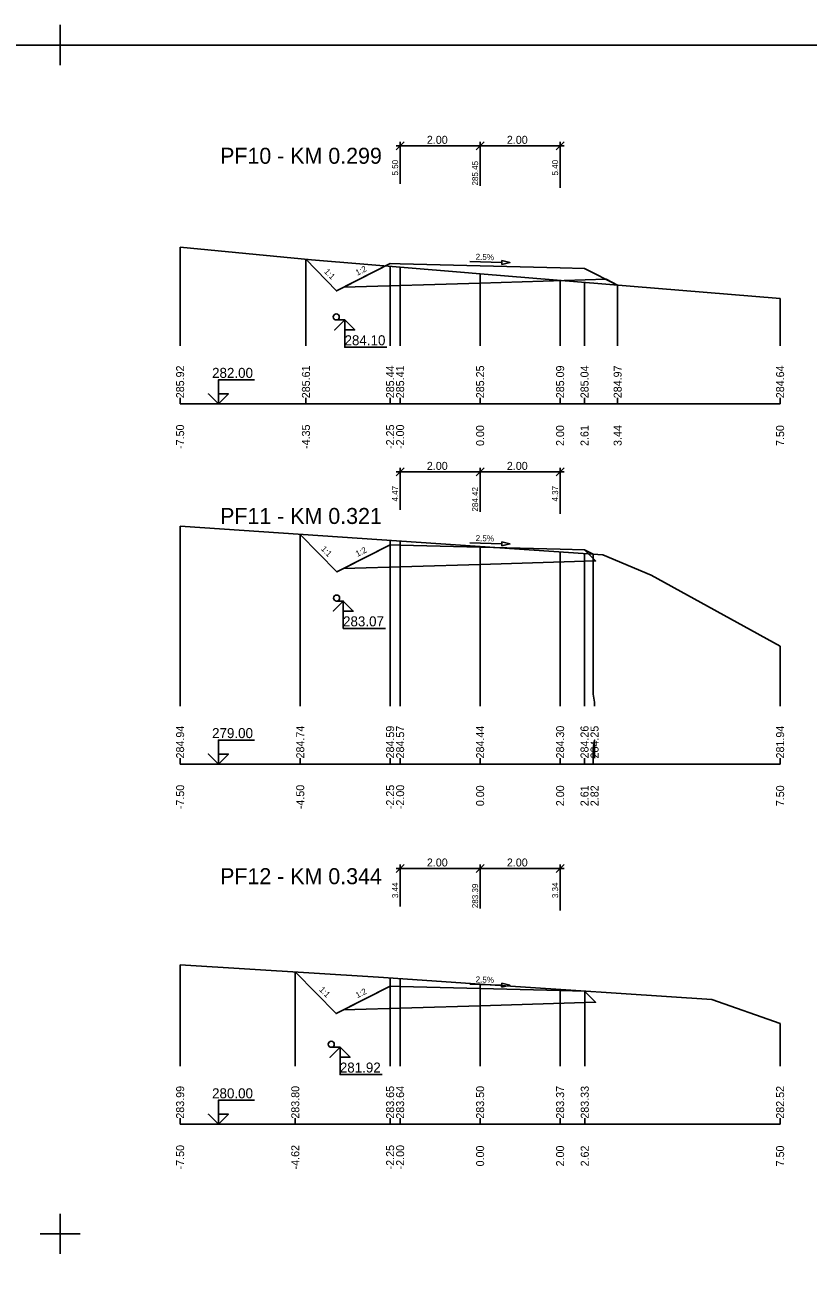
# Model space of a CAD drawing. Extents: x -5 to 1895, y -2 to 602.
# Drawn here: x 621.2 to 817, y 289.4 to 601.7 of the extents above; entities that cross this region are included whole.
import ezdxf

# ---------------------------------------------------------------- set-up
doc = ezdxf.new("R2010")
doc.units = 0
for name, color, linetype in [('KOTA', 7, 'Continuous'), ('KOTA_DELKY', 7, 'Continuous'), ('KOTA_DELKY_CONT', 7, 'Continuous'), ('KRIZENI', 7, 'Continuous'), ('NS_TELESO_VOZOVKY', 7, 'Continuous'), ('NS_V_PF', 7, 'Continuous'), ('REZY_PF_PUVODNI', 7, 'Continuous'), ('SESTAVY_REZU_PF', 7, 'Continuous'), ('SKLON', 7, 'Continuous'), ('SVK', 7, 'Continuous')]:
    doc.layers.add(name, color=color, linetype=linetype)

msp = doc.modelspace()

# ---------------------------------------------------------------- linework, layer by layer
for p, q in [((630, 601.67), (630, 591.67)), ((630, 601.67), (630, 591.67)), ((630, 601.67), (630, 591.67)), ((630, 601.67), (630, 591.67)), ((630, 601.67), (630, 591.67)), ((630, 601.67), (630, 591.67)), ((630, 601.67), (630, 591.67)), ((630, 601.67), (630, 591.67)), ((630, 601.67), (630, 591.67)), ((630, 601.67), (630, 591.67)), ((630, 601.67), (630, 591.67)), ((630, 601.67), (630, 591.67)), ((630, 601.67), (630, 591.67)), ((630, 601.67), (630, 591.67)), ((630, 601.67), (630, 591.67)), ((630, 601.67), (630, 591.67)), ((630, 601.67), (630, 591.67)), ((630, 601.67), (630, 591.67)), ((630, 601.67), (630, 591.67)), ((630, 601.67), (630, 591.67)), ((630, 601.67), (630, 591.67)), ((630, 601.67), (630, 591.67)), ((630, 601.67), (630, 591.67)), ((630, 601.67), (630, 591.67)), ((630, 601.67), (630, 591.67)), ((630, 601.67), (630, 591.67)), ((630, 601.67), (630, 591.67)), ((630, 601.67), (630, 591.67)), ((630, 601.67), (630, 591.67)), ((630, 601.67), (630, 591.67)), ((630, 601.67), (630, 591.67)), ((630, 601.67), (630, 591.67)), ((630, 601.67), (630, 591.67)), ((630, 601.67), (630, 591.67)), ((630, 601.67), (630, 591.67)), ((630, 601.67), (630, 591.67)), ((630, 601.67), (630, 591.67)), ((630, 601.67), (630, 591.67)), ((630, 601.67), (630, 591.67)), ((630, 601.67), (630, 591.67)), ((630, 601.67), (630, 591.67)), ((630, 601.67), (630, 591.67)), ((630, 601.67), (630, 591.67)), ((630, 601.67), (630, 591.67)), ((630, 601.67), (630, 591.67)), ((630, 601.67), (630, 591.67)), ((630, 601.67), (630, 591.67)), ((630, 601.67), (630, 591.67)), ((630, 601.67), (630, 591.67)), ((630, 601.67), (630, 591.67)), ((630, 601.67), (630, 591.67)), ((630, 601.67), (630, 591.67)), ((630, 601.67), (630, 591.67)), ((630, 601.67), (630, 591.67)), ((635, 596.67), (625, 596.67)), ((635, 596.67), (625, 596.67)), ((635, 596.67), (625, 596.67)), ((635, 596.67), (625, 596.67)), ((635, 596.67), (625, 596.67)), ((635, 596.67), (625, 596.67)), ((635, 596.67), (625, 596.67)), ((635, 596.67), (625, 596.67)), ((635, 596.67), (625, 596.67)), ((635, 596.67), (625, 596.67)), ((635, 596.67), (625, 596.67)), ((635, 596.67), (625, 596.67)), ((635, 596.67), (625, 596.67)), ((635, 596.67), (625, 596.67)), ((635, 596.67), (625, 596.67)), ((635, 596.67), (625, 596.67)), ((635, 596.67), (625, 596.67)), ((635, 596.67), (625, 596.67)), ((635, 596.67), (625, 596.67)), ((635, 596.67), (625, 596.67)), ((635, 596.67), (625, 596.67)), ((635, 596.67), (625, 596.67)), ((635, 596.67), (625, 596.67)), ((635, 596.67), (625, 596.67)), ((635, 596.67), (625, 596.67)), ((635, 596.67), (625, 596.67)), ((635, 596.67), (625, 596.67)), ((635, 596.67), (625, 596.67)), ((635, 596.67), (625, 596.67)), ((635, 596.67), (625, 596.67)), ((635, 596.67), (625, 596.67)), ((635, 596.67), (625, 596.67)), ((635, 596.67), (625, 596.67)), ((635, 596.67), (625, 596.67)), ((635, 596.67), (625, 596.67)), ((635, 596.67), (625, 596.67)), ((635, 596.67), (625, 596.67)), ((635, 596.67), (625, 596.67)), ((635, 596.67), (625, 596.67)), ((635, 596.67), (625, 596.67)), ((635, 596.67), (625, 596.67)), ((635, 596.67), (625, 596.67)), ((635, 596.67), (625, 596.67)), ((635, 596.67), (625, 596.67)), ((635, 596.67), (625, 596.67)), ((635, 596.67), (625, 596.67)), ((635, 596.67), (625, 596.67)), ((635, 596.67), (625, 596.67)), ((635, 596.67), (625, 596.67)), ((635, 596.67), (625, 596.67)), ((635, 596.67), (625, 596.67)), ((635, 596.67), (625, 596.67)), ((635, 596.67), (625, 596.67)), ((635, 596.67), (625, 596.67)), ((630, 304.67), (630, 294.67)), ((630, 304.67), (630, 294.67)), ((630, 304.67), (630, 294.67)), ((630, 304.67), (630, 294.67)), ((630, 304.67), (630, 294.67)), ((630, 304.67), (630, 294.67)), ((630, 304.67), (630, 294.67)), ((630, 304.67), (630, 294.67)), ((630, 304.67), (630, 294.67)), ((630, 304.67), (630, 294.67)), ((630, 304.67), (630, 294.67)), ((630, 304.67), (630, 294.67)), ((630, 304.67), (630, 294.67)), ((630, 304.67), (630, 294.67)), ((630, 304.67), (630, 294.67)), ((630, 304.67), (630, 294.67)), ((630, 304.67), (630, 294.67)), ((630, 304.67), (630, 294.67)), ((630, 304.67), (630, 294.67)), ((630, 304.67), (630, 294.67)), ((630, 304.67), (630, 294.67)), ((630, 304.67), (630, 294.67)), ((630, 304.67), (630, 294.67)), ((630, 304.67), (630, 294.67)), ((630, 304.67), (630, 294.67)), ((630, 304.67), (630, 294.67)), ((630, 304.67), (630, 294.67)), ((630, 304.67), (630, 294.67)), ((630, 304.67), (630, 294.67)), ((630, 304.67), (630, 294.67)), ((630, 304.67), (630, 294.67)), ((630, 304.67), (630, 294.67)), ((630, 304.67), (630, 294.67)), ((630, 304.67), (630, 294.67)), ((630, 304.67), (630, 294.67)), ((630, 304.67), (630, 294.67)), ((630, 304.67), (630, 294.67)), ((630, 304.67), (630, 294.67)), ((630, 304.67), (630, 294.67)), ((630, 304.67), (630, 294.67)), ((630, 304.67), (630, 294.67)), ((630, 304.67), (630, 294.67)), ((630, 304.67), (630, 294.67)), ((630, 304.67), (630, 294.67)), ((630, 304.67), (630, 294.67)), ((630, 304.67), (630, 294.67)), ((630, 304.67), (630, 294.67)), ((630, 304.67), (630, 294.67)), ((630, 304.67), (630, 294.67)), ((630, 304.67), (630, 294.67)), ((630, 304.67), (630, 294.67)), ((630, 304.67), (630, 294.67)), ((630, 304.67), (630, 294.67)), ((630, 304.67), (630, 294.67)), ((635, 299.67), (625, 299.67)), ((635, 299.67), (625, 299.67)), ((635, 299.67), (625, 299.67)), ((635, 299.67), (625, 299.67)), ((635, 299.67), (625, 299.67)), ((635, 299.67), (625, 299.67)), ((635, 299.67), (625, 299.67)), ((635, 299.67), (625, 299.67)), ((635, 299.67), (625, 299.67)), ((635, 299.67), (625, 299.67)), ((635, 299.67), (625, 299.67)), ((635, 299.67), (625, 299.67)), ((635, 299.67), (625, 299.67)), ((635, 299.67), (625, 299.67)), ((635, 299.67), (625, 299.67)), ((635, 299.67), (625, 299.67)), ((635, 299.67), (625, 299.67)), ((635, 299.67), (625, 299.67)), ((635, 299.67), (625, 299.67)), ((635, 299.67), (625, 299.67)), ((635, 299.67), (625, 299.67)), ((635, 299.67), (625, 299.67)), ((635, 299.67), (625, 299.67)), ((635, 299.67), (625, 299.67)), ((635, 299.67), (625, 299.67)), ((635, 299.67), (625, 299.67)), ((635, 299.67), (625, 299.67)), ((635, 299.67), (625, 299.67)), ((635, 299.67), (625, 299.67)), ((635, 299.67), (625, 299.67)), ((635, 299.67), (625, 299.67)), ((635, 299.67), (625, 299.67)), ((635, 299.67), (625, 299.67)), ((635, 299.67), (625, 299.67)), ((635, 299.67), (625, 299.67)), ((635, 299.67), (625, 299.67)), ((635, 299.67), (625, 299.67)), ((635, 299.67), (625, 299.67)), ((635, 299.67), (625, 299.67)), ((635, 299.67), (625, 299.67)), ((635, 299.67), (625, 299.67)), ((635, 299.67), (625, 299.67)), ((635, 299.67), (625, 299.67)), ((635, 299.67), (625, 299.67)), ((635, 299.67), (625, 299.67)), ((635, 299.67), (625, 299.67)), ((635, 299.67), (625, 299.67)), ((635, 299.67), (625, 299.67)), ((635, 299.67), (625, 299.67)), ((635, 299.67), (625, 299.67)), ((635, 299.67), (625, 299.67)), ((635, 299.67), (625, 299.67)), ((635, 299.67), (625, 299.67)), ((635, 299.67), (625, 299.67))]:
    msp.add_line(p, q)
msp.add_lwpolyline([(0, 596.67), (1890, 596.67), (1890, 2.67), (0, 2.67)], close=True)
at = {"layer": 'KOTA'}
for points in [[(701.14, 527.97), (698.64, 525.47), (701.14, 527.97), (701.14, 521.15), (711.69, 521.15)], [(699.03, 527.97), (701.14, 527.97)], [(701.14, 527.97), (703.64, 525.47), (701.14, 525.47), (701.14, 527.97)], [(701.14, 527.97), (703.64, 525.47), (701.14, 525.47)], [(669.57, 507), (667.07, 509.5), (669.57, 507), (669.57, 513), (678.57, 513)], [(669.57, 507), (672.07, 509.5), (669.57, 509.5), (669.57, 507)], [(669.57, 507), (672.07, 509.5), (669.57, 509.5)], [(700.78, 457.74), (698.28, 455.24), (700.78, 457.74), (700.78, 450.92), (711.32, 450.92)], [(699.13, 457.74), (700.78, 457.74)], [(700.78, 457.74), (703.28, 455.24), (700.78, 455.24), (700.78, 457.74)], [(700.78, 457.74), (703.28, 455.24), (700.78, 455.24)], [(669.57, 417), (667.07, 419.5), (669.57, 417), (669.57, 423), (678.57, 423)], [(669.57, 417), (672.07, 419.5), (669.57, 419.5), (669.57, 417)], [(669.57, 417), (672.07, 419.5), (669.57, 419.5)], [(699.97, 346.25), (697.47, 343.75), (699.97, 346.25), (699.97, 339.43), (710.51, 339.43)], [(697.79, 346.25), (699.97, 346.25)], [(699.97, 346.25), (702.47, 343.75), (699.97, 343.75), (699.97, 346.25)], [(699.97, 346.25), (702.47, 343.75), (699.97, 343.75)], [(669.57, 327), (667.07, 329.5), (669.57, 327), (669.57, 333), (678.57, 333)], [(669.57, 327), (672.07, 329.5), (669.57, 329.5), (669.57, 327)], [(669.57, 327), (672.07, 329.5), (669.57, 329.5)]]:
    msp.add_lwpolyline(points, dxfattribs=at)
at = {"layer": 'KOTA_DELKY'}
for points in [[(714, 570.48), (716, 572.48)], [(715, 561.98), (715, 572.48)], [(734, 570.48), (736, 572.48)], [(734, 570.48), (736, 572.48)], [(735, 561.48), (735, 572.48)], [(735, 561.48), (735, 572.48)], [(754, 570.48), (756, 572.48)], [(755, 560.98), (755, 572.48)], [(714, 571.48), (736, 571.48)], [(734, 571.48), (756, 571.48)], [(714, 489.01), (716, 491.01)], [(715, 480.51), (715, 491.01)], [(734, 489.01), (736, 491.01)], [(734, 489.01), (736, 491.01)], [(735, 480.01), (735, 491.01)], [(735, 480.01), (735, 491.01)], [(754, 489.01), (756, 491.01)], [(755, 479.51), (755, 491.01)], [(714, 490.01), (736, 490.01)], [(734, 490.01), (756, 490.01)], [(714, 389.92), (716, 391.92)], [(714, 390.92), (736, 390.92)], [(715, 381.42), (715, 391.92)], [(734, 389.92), (736, 391.92)], [(734, 389.92), (736, 391.92)], [(734, 390.92), (756, 390.92)], [(735, 380.92), (735, 391.92)], [(735, 380.92), (735, 391.92)], [(754, 389.92), (756, 391.92)], [(755, 380.42), (755, 391.92)]]:
    msp.add_lwpolyline(points, dxfattribs=at)
at = {"layer": 'KRIZENI'}
for centre in [(699.03, 528.72), (699.13, 458.49), (697.79, 347)]:
    msp.add_circle(centre, 0.75, dxfattribs=at)
at = {"layer": 'NS_TELESO_VOZOVKY'}
for points in [[(735, 541.48), (755, 540.98), (761.1, 540.83), (769.38, 536.69), (766.5, 538.13), (735, 537.18), (700.92, 536.16), (712.5, 542.04), (715, 541.98), (735, 541.48)], [(735, 471.2), (755, 470.7), (761.1, 470.55), (763.88, 467.77), (735, 466.9), (700.86, 465.88), (712.5, 471.77), (715, 471.7), (735, 471.2)], [(735, 360.92), (755, 360.42), (761.1, 360.27), (763.88, 357.49), (735, 356.62), (700.86, 355.6), (712.5, 361.49), (715, 361.42), (735, 360.92)]]:
    msp.add_lwpolyline(points, dxfattribs=at)
at = {"layer": 'NS_V_PF'}
for points in [[(691.45, 543.12), (699.08, 535.22), (712.5, 542.04), (715, 541.98), (735, 541.48), (755, 540.98), (761.1, 540.83), (769.38, 536.69)], [(690.04, 474.4), (699.19, 465.04), (712.5, 471.77), (715, 471.7), (735, 471.2), (755, 470.7), (761.1, 470.55), (763.24, 469.48)], [(688.82, 365.05), (699.01, 354.66), (712.5, 361.49), (715, 361.42), (735, 360.92), (755, 360.42), (761.1, 360.27), (761.16, 360.3)]]:
    msp.add_lwpolyline(points, dxfattribs=at)
at = {"layer": 'REZY_PF_PUVODNI'}
for points in [[(660, 546.17), (692.85, 542.98), (730.08, 539.9), (735, 539.5), (735, 539.5), (810, 533.37)], [(660, 476.42), (735, 471.38), (735, 471.38), (765.65, 469.32), (777.79, 464.19), (810, 446.43)], [(660, 366.86), (709.57, 363.74), (735, 362.05), (792.95, 358.19), (810, 352.18)]]:
    msp.add_lwpolyline(points, dxfattribs=at)
at = {"layer": 'SESTAVY_REZU_PF'}
for points in [[(660, 507), (810, 507)], [(660, 417), (810, 417)], [(660, 327), (810, 327)]]:
    msp.add_lwpolyline(points, dxfattribs=at)
at = {"layer": 'SKLON'}
for points in [[(732.45, 542.55), (740.45, 542.35)], [(740.46, 542.85), (742.45, 542.3), (740.43, 541.85), (740.46, 542.85)], [(732.45, 472.27), (740.45, 472.07)], [(740.46, 472.57), (742.45, 472.02), (740.43, 471.57), (740.46, 472.57)], [(740.46, 362.29), (742.45, 361.74), (740.43, 361.29), (740.46, 362.29)], [(732.45, 361.99), (740.45, 361.79)]]:
    msp.add_lwpolyline(points, dxfattribs=at)
for points in [[(740.46, 542.85), (742.45, 542.3), (740.43, 541.85)], [(740.46, 472.57), (742.45, 472.02), (740.43, 471.57)], [(740.46, 362.29), (742.45, 361.74), (740.43, 361.29)]]:
    msp.add_lwpolyline(points, close=True, dxfattribs=at)
at = {"layer": 'SVK'}
for points in [[(660, 521.5), (660, 546.17)], [(691.45, 521.5), (691.45, 543.12)], [(712.5, 521.5), (712.5, 541.36)], [(715, 521.5), (715, 541.15)], [(735, 521.5), (735, 539.5)], [(755, 521.5), (755, 537.86)], [(761.1, 521.5), (761.1, 537.37)], [(769.38, 521.5), (769.38, 536.69)], [(810, 521.5), (810, 533.37)], [(660, 507), (660, 508.5)], [(691.45, 507), (691.45, 508.5)], [(712.5, 507), (712.5, 508.5)], [(715, 507), (715, 508.5)], [(735, 507), (735, 508.5)], [(755, 507), (755, 508.5)], [(761.1, 507), (761.1, 508.5)], [(769.38, 507), (769.38, 508.5)], [(810, 507), (810, 508.5)], [(660, 431.5), (660, 476.42)], [(690.03, 431.5), (690.03, 474.4)], [(712.5, 431.5), (712.5, 472.89)], [(715, 431.5), (715, 472.72)], [(735, 431.5), (735, 471.38)], [(755, 431.5), (755, 470.03)], [(761.1, 431.5), (761.1, 469.62)], [(763.6, 431.5), (763.6, 432.5), (763.24, 434.5), (763.24, 469.48)], [(810, 431.5), (810, 446.43)], [(763.24, 417), (763.24, 421), (763.6, 423), (763.6, 418.5)], [(660, 417), (660, 418.5)], [(690.03, 417), (690.03, 418.5)], [(712.5, 417), (712.5, 418.5)], [(715, 417), (715, 418.5)], [(735, 417), (735, 418.5)], [(755, 417), (755, 418.5)], [(761.1, 417), (761.1, 418.5)], [(810, 417), (810, 418.5)], [(660, 341.5), (660, 366.86)], [(688.79, 341.5), (688.79, 365.05)], [(712.5, 341.5), (712.5, 363.54)], [(715, 341.5), (715, 363.38)], [(735, 341.5), (735, 362.05)], [(755, 341.5), (755, 360.71)], [(761.16, 341.5), (761.16, 360.3)], [(810, 341.5), (810, 352.18)], [(660, 327), (660, 328.5)], [(688.79, 327), (688.79, 328.5)], [(712.5, 327), (712.5, 328.5)], [(715, 327), (715, 328.5)], [(735, 327), (735, 328.5)], [(755, 327), (755, 328.5)], [(761.16, 327), (761.16, 328.5)], [(810, 327), (810, 328.5)]]:
    msp.add_lwpolyline(points, dxfattribs=at)

# ---------------------------------------------------------------- texts
at = {"layer": 'KOTA'}
for s, p in [('284.10', (701.1, 521.65)), ('282.00', (667.99, 513.5)), ('283.07', (700.73, 451.42)), ('279.00', (667.99, 423.5)), ('281.92', (699.93, 339.93)), ('280.00', (667.99, 333.5))]:
    msp.add_text(s, height=2.5, dxfattribs=at).set_placement(p)
at = {"layer": 'KOTA_DELKY'}
for p in [(721.69, 571.98), (741.69, 571.98), (721.69, 490.51), (741.69, 490.51), (721.69, 391.42), (741.69, 391.42)]:
    msp.add_text('2.00', height=2, dxfattribs=at).set_placement(p)
at = {"layer": 'KOTA_DELKY_CONT'}
for s, p in [('5.50', (714.5, 564.07)), ('285.45', (734.5, 561.56)), ('5.40', (754.5, 564.07)), ('4.47', (714.5, 482.6)), ('284.42', (734.5, 480.09)), ('4.37', (754.5, 482.6)), ('3.44', (714.5, 383.51)), ('3.34', (754.5, 383.51)), ('283.39', (734.5, 381))]:
    msp.add_text(s, height=1.5, rotation=90, dxfattribs=at).set_placement(p)
at = {"layer": 'SESTAVY_REZU_PF'}
for s, p in [('PF10 - KM 0.299', (670, 567)), ('PF11 - KM 0.321', (670, 477)), ('PF12 - KM 0.344', (670, 387))]:
    msp.add_text(s, height=4, dxfattribs=at).set_placement(p)
at = {"layer": 'SKLON'}
for s, rotation, p in [('2.5%', 358.5679, (733.87, 543.01)), ('1:1', 313.9941, (695.9, 539.95)), ('1:2', 26.9444, (704.32, 539.01)), ('2.5%', 358.5679, (733.87, 472.73)), ('1:1', 314.326, (695.1, 470.65)), ('1:2', 26.8191, (704.32, 468.75)), ('2.5%', 358.5679, (733.87, 362.45)), ('1:1', 314.4526, (694.65, 360.54)), ('1:2', 26.8284, (704.32, 358.47))]:
    msp.add_text(s, height=1.5, rotation=rotation, dxfattribs=at).set_placement(p)
at = {"layer": 'SVK'}
for s, p in [(' 285.92', (661, 507.67)), (' 285.61', (692.45, 507.67)), (' 285.44', (713.5, 507.67)), (' 285.41', (716, 507.67)), (' 285.25', (736, 507.67)), (' 285.09', (756, 507.67)), (' 285.04', (762.1, 507.67)), (' 284.97', (770.38, 507.67)), (' 284.64', (811, 507.67)), (' -7.50', (661, 495)), (' -4.35', (692.45, 495)), (' -2.25', (713.5, 495)), (' -2.00', (716, 495)), ('  0.00', (736, 495)), ('  2.00', (756, 495)), ('  2.61', (762.1, 495)), ('  3.44', (770.38, 495)), ('  7.50', (811, 495)), (' 284.94', (661, 417.67)), (' 284.74', (691.03, 417.67)), (' 284.59', (713.5, 417.67)), (' 284.57', (716, 417.67)), (' 284.44', (736, 417.67)), (' 284.30', (756, 417.67)), (' 284.26', (762.1, 417.67)), (' 284.25', (764.6, 417.67)), (' 281.94', (811, 417.67)), (' -7.50', (661, 405)), (' -4.50', (691.03, 405)), (' -2.25', (713.5, 405)), (' -2.00', (716, 405)), ('  0.00', (736, 405)), ('  2.00', (756, 405)), ('  2.61', (762.1, 405)), ('  2.82', (764.6, 405)), ('  7.50', (811, 405)), (' 283.99', (661, 327.67)), (' 283.80', (689.79, 327.67)), (' 283.65', (713.5, 327.67)), (' 283.64', (716, 327.67)), (' 283.50', (736, 327.67)), (' 283.37', (756, 327.67)), (' 283.33', (762.16, 327.67)), (' 282.52', (811, 327.67)), (' -7.50', (661, 315)), (' -4.62', (689.79, 315)), (' -2.25', (713.5, 315)), (' -2.00', (716, 315)), ('  0.00', (736, 315)), ('  2.00', (756, 315)), ('  2.62', (762.16, 315)), ('  7.50', (811, 315))]:
    msp.add_text(s, height=2, rotation=90, dxfattribs=at).set_placement(p)

doc.saveas('drawing.dxf')
